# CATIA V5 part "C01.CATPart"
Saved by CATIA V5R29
Part number: C01
Source: Unknown
Bounding box of the stored display mesh (mm): x -30 to 30, y -40 to 40, z -30 to 230
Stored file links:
  C:\가치같이\SmartFactory_BoxErectorConveyor\Boxing(under)\C01.CATPart
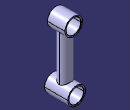
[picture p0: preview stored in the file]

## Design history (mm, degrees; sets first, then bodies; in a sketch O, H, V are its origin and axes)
Body1 (main body)
  Solid1 "PartBody": solid without history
